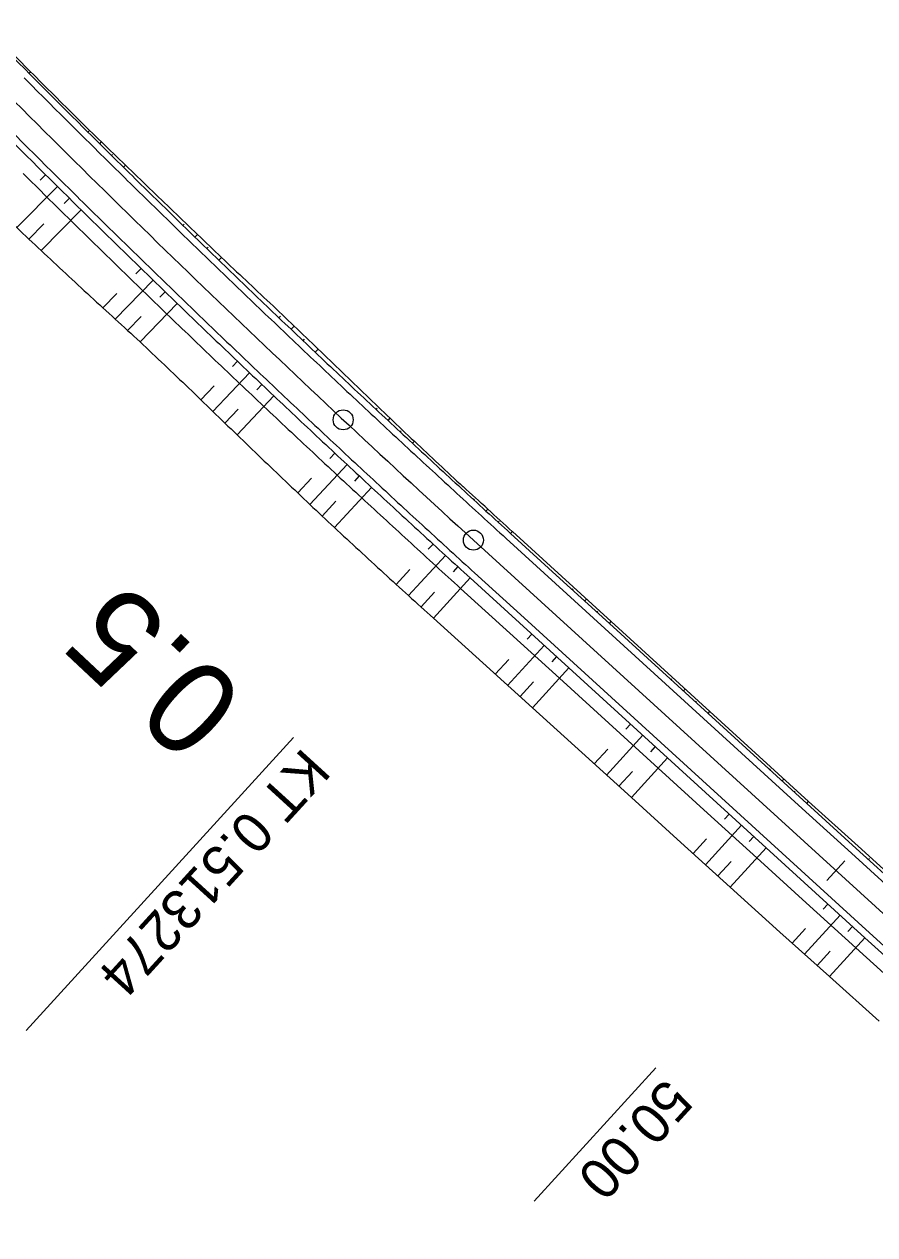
# Model space of a CAD drawing. Extents: x -481656 to -478728, y -1113199 to -1110710.
# Drawn here: x -481388.3 to -481324.6, y -1112998.4 to -1112907.7 of the extents above; entities that cross this region are included whole.
import ezdxf

# ---------------------------------------------------------------- set-up
doc = ezdxf.new("R2010")
doc.units = 0
for name, color, linetype in [('C11_HATCH_SLOPE_L', 7, 'Continuous'), ('C11_HATCH_SLOPE_R', 7, 'Continuous'), ('C11_HECTOMETRY', 7, 'Continuous'), ('C11_HLBODY', 7, 'Continuous'), ('C11_HRANA_TELESO', 7, 'Continuous'), ('C11_KORUNA', 7, 'Continuous'), ('C11_OSA', 7, 'Continuous'), ('C11_PRIKOP', 7, 'Continuous'), ('C11_STANICENI', 7, 'Continuous'), ('C11_VOZOVKA', 7, 'Continuous'), ('C11_ZPEVKRAJ', 7, 'Continuous')]:
    doc.layers.add(name, color=color, linetype=linetype)

msp = doc.modelspace()

# ---------------------------------------------------------------- linework, layer by layer
at = {"layer": 'C11_HATCH_SLOPE_L'}
for p, q in [((-481387.958, -1112911.412), (-481387.842, -1112911.297)), ((-481383.545, -1112915.818), (-481383.481, -1112915.754)), ((-481383.418, -1112915.69), (-481383.418, -1112915.69)), ((-481382.659, -1112916.696), (-481382.526, -1112916.561)), ((-481381.772, -1112917.572), (-481381.702, -1112917.501)), ((-481381.632, -1112917.43), (-481381.632, -1112917.43)), ((-481380.884, -1112918.448), (-481380.737, -1112918.299)), ((-481376.427, -1112922.81), (-481376.337, -1112922.717)), ((-481376.247, -1112922.624), (-481376.247, -1112922.624)), ((-481375.533, -1112923.679), (-481375.346, -1112923.486)), ((-481374.637, -1112924.546), (-481374.54, -1112924.446)), ((-481374.443, -1112924.346), (-481374.443, -1112924.346)), ((-481373.74, -1112925.413), (-481373.54, -1112925.206)), ((-481369.24, -1112929.73), (-481369.125, -1112929.609)), ((-481369.01, -1112929.488), (-481369.01, -1112929.488)), ((-481368.336, -1112930.59), (-481368.108, -1112930.35)), ((-481367.432, -1112931.449), (-481367.318, -1112931.33)), ((-481367.205, -1112931.21), (-481367.205, -1112931.21)), ((-481366.527, -1112932.306), (-481366.301, -1112932.068)), ((-481361.811, -1112936.394), (-481361.811, -1112936.394)), ((-481361.983, -1112936.578), (-481361.897, -1112936.486)), ((-481361.072, -1112937.429), (-481360.91, -1112937.255)), ((-481360.159, -1112938.279), (-481360.083, -1112938.198)), ((-481360.007, -1112938.116), (-481360.007, -1112938.116)), ((-481359.245, -1112939.127), (-481359.103, -1112938.975)), ((-481354.659, -1112943.353), (-481354.596, -1112943.284)), ((-481354.534, -1112943.216), (-481354.534, -1112943.216)), ((-481353.739, -1112944.195), (-481353.613, -1112944.058)), ((-481352.817, -1112945.036), (-481352.754, -1112944.968)), ((-481352.691, -1112944.899), (-481352.691, -1112944.899)), ((-481351.893, -1112945.879), (-481351.767, -1112945.741)), ((-481347.149, -1112949.952), (-481347.149, -1112949.952)), ((-481347.275, -1112950.09), (-481347.212, -1112950.021)), ((-481346.352, -1112950.933), (-481346.225, -1112950.794)), ((-481345.428, -1112951.775), (-481345.365, -1112951.706)), ((-481345.302, -1112951.636), (-481345.302, -1112951.636)), ((-481344.504, -1112952.617), (-481344.378, -1112952.478)), ((-481339.887, -1112956.829), (-481339.823, -1112956.759)), ((-481339.759, -1112956.689), (-481339.759, -1112956.689)), ((-481338.963, -1112957.671), (-481338.835, -1112957.531)), ((-481338.04, -1112958.514), (-481337.976, -1112958.444)), ((-481337.911, -1112958.373), (-481337.911, -1112958.373)), ((-481337.116, -1112959.356), (-481336.988, -1112959.215)), ((-481332.498, -1112963.568), (-481332.434, -1112963.497)), ((-481332.369, -1112963.426), (-481332.369, -1112963.426)), ((-481331.575, -1112964.41), (-481331.445, -1112964.268)), ((-481330.651, -1112965.252), (-481330.586, -1112965.181)), ((-481330.521, -1112965.11), (-481330.521, -1112965.11)), ((-481329.727, -1112966.095), (-481329.598, -1112965.952)), ((-481325.11, -1112970.306), (-481325.036, -1112970.225)), ((-481324.962, -1112970.144), (-481324.962, -1112970.144))]:
    msp.add_line(p, q, dxfattribs=at)
at = {"layer": 'C11_HATCH_SLOPE_R'}
for p, q in [((-481386.715, -1112919.012), (-481387.108, -1112919.409)), ((-481385.825, -1112919.894), (-481388.87, -1112922.972)), ((-481384.934, -1112920.775), (-481385.326, -1112921.172)), ((-481384.042, -1112921.654), (-481387.04, -1112924.699)), ((-481386.836, -1112922.702), (-481387.956, -1112923.836)), ((-481379.565, -1112926.036), (-481379.951, -1112926.432)), ((-481378.666, -1112926.909), (-481381.499, -1112929.829)), ((-481381.382, -1112927.904), (-481382.428, -1112928.98)), ((-481377.766, -1112927.78), (-481378.15, -1112928.176)), ((-481376.865, -1112928.651), (-481379.638, -1112931.524)), ((-481379.551, -1112929.625), (-481380.569, -1112930.677)), ((-481372.345, -1112932.987), (-481372.722, -1112933.383)), ((-481371.437, -1112933.851), (-481374.186, -1112936.742)), ((-481374.094, -1112934.822), (-481375.089, -1112935.866)), ((-481370.529, -1112934.714), (-481370.904, -1112935.11)), ((-481369.619, -1112935.575), (-481372.378, -1112938.491)), ((-481372.282, -1112936.562), (-481373.283, -1112937.617)), ((-481365.056, -1112939.866), (-481365.426, -1112940.262)), ((-481364.14, -1112940.721), (-481366.922, -1112943.706)), ((-481366.814, -1112941.748), (-481367.834, -1112942.84)), ((-481363.223, -1112941.574), (-481363.59, -1112941.97)), ((-481362.305, -1112942.427), (-481365.094, -1112945.435)), ((-481364.983, -1112943.468), (-481366.009, -1112944.571)), ((-481357.698, -1112946.672), (-481358.06, -1112947.067)), ((-481356.774, -1112947.517), (-481359.531, -1112950.536)), ((-481359.442, -1112948.576), (-481360.462, -1112949.69)), ((-481355.849, -1112948.361), (-481356.209, -1112948.756)), ((-481354.925, -1112949.203), (-481357.676, -1112952.219)), ((-481357.586, -1112950.265), (-481358.602, -1112951.38)), ((-481350.308, -1112953.415), (-481350.665, -1112953.806)), ((-481349.384, -1112954.257), (-481352.119, -1112957.256)), ((-481352.034, -1112955.307), (-481353.045, -1112956.416)), ((-481348.46, -1112955.1), (-481348.816, -1112955.49)), ((-481347.537, -1112955.942), (-481350.266, -1112958.935)), ((-481350.182, -1112956.988), (-481351.192, -1112958.095)), ((-481342.919, -1112960.154), (-481343.272, -1112960.541)), ((-481341.996, -1112960.996), (-481344.71, -1112963.973)), ((-481344.63, -1112962.03), (-481345.636, -1112963.133)), ((-481340.148, -1112962.681), (-481342.858, -1112965.651)), ((-481341.072, -1112961.838), (-481341.424, -1112962.224)), ((-481342.78, -1112963.712), (-481343.784, -1112964.812)), ((-481335.531, -1112966.892), (-481335.88, -1112967.275)), ((-481334.607, -1112967.735), (-481337.301, -1112970.689)), ((-481337.228, -1112968.754), (-481338.228, -1112969.85)), ((-481333.683, -1112968.577), (-481334.032, -1112968.959)), ((-481332.76, -1112969.42), (-481335.449, -1112972.368)), ((-481335.378, -1112970.434), (-481336.375, -1112971.528)), ((-481327.219, -1112974.474), (-481329.884, -1112977.396)), ((-481328.142, -1112973.631), (-481328.488, -1112974.01)), ((-481326.295, -1112975.316), (-481326.64, -1112975.694)), ((-481329.824, -1112975.474), (-481330.814, -1112976.561)), ((-481325.371, -1112976.158), (-481328.022, -1112979.065)), ((-481327.968, -1112977.15), (-481328.953, -1112978.23))]:
    msp.add_line(p, q, dxfattribs=at)
at = {"layer": 'C11_HECTOMETRY'}
msp.add_circle((-481364.432, -1112937.368), 0.75, dxfattribs=at)
at = {"layer": 'C11_HLBODY'}
msp.add_line((-481368.162, -1112961.155), (-481388.176, -1112983.098), dxfattribs=at)
msp.add_circle((-481354.685, -1112946.378), 0.75, dxfattribs=at)
at = {"layer": 'C11_HRANA_TELESO'}
for p, q in [((-481351.767, -1112945.741), (-481348.073, -1112949.11)), ((-481348.073, -1112949.11), (-481344.378, -1112952.478)), ((-481357.676, -1112952.219), (-481353.971, -1112955.577)), ((-481344.378, -1112952.478), (-481340.683, -1112955.847)), ((-481353.971, -1112955.577), (-481350.266, -1112958.935)), ((-481340.683, -1112955.847), (-481336.988, -1112959.215)), ((-481350.266, -1112958.935), (-481346.563, -1112962.294)), ((-481336.988, -1112959.215), (-481333.292, -1112962.584)), ((-481346.563, -1112962.294), (-481342.858, -1112965.651)), ((-481333.292, -1112962.584), (-481329.598, -1112965.952)), ((-481342.858, -1112965.651), (-481339.154, -1112969.01)), ((-481329.598, -1112965.952), (-481325.886, -1112969.303)), ((-481339.154, -1112969.01), (-481335.449, -1112972.368)), ((-481325.886, -1112969.303), (-481322.188, -1112972.668)), ((-481335.449, -1112972.368), (-481331.745, -1112975.727)), ((-481331.745, -1112975.727), (-481328.022, -1112979.065)), ((-481328.022, -1112979.065), (-481324.301, -1112982.404))]:
    msp.add_line(p, q, dxfattribs=at)
for centre, radius, start, end in [((-479258.593, -1110808.225), 2992.76, 224.550017, 224.645628), ((-480681.84, -1112206.504), 997.583, 224.950853, 225.237333), ((-480686.361, -1112202.081), 997.56, 225.600597, 225.887086), ((-480686.387, -1112202.11), 997.521, 225.886986, 226.173475), ((-480697.007, -1112191.858), 1006.58, 226.436722, 226.723272), ((-480686.557, -1112202.001), 997.482, 226.184886, 226.471375), ((-480699.383, -1112189.792), 1006.459, 226.902394, 227.188967), ((-480687.664, -1112201.012), 997.438, 226.556611, 226.843103), ((-480703.004, -1112186.645), 1006.319, 227.461944, 227.748556), ((-480679.681, -1112208.608), 997.418, 226.210094, 226.496575), ((-480684.812, -1112203.71), 1006.229, 226.328314, 226.614797), ((-480672.042, -1112215.887), 997.453, 225.890458, 226.176958), ((-480673.733, -1112214.328), 1006.239, 225.741017, 226.027511), ((-480672.182, -1112215.67), 997.513, 226.191403, 226.477903), ((-480674.239, -1112213.774), 1006.287, 226.070111, 226.356603), ((-480677.508, -1112210.593), 997.554, 226.9005, 227.186983), ((-480674.506, -1112213.458), 1006.331, 226.380047, 226.666536), ((-481690.021, -1113312.304), 498.782, 47.30015, 47.87359), ((-480681.85, -1112206.573), 1006.349, 227.239672, 227.526153), ((-481021.065, -1112578.22), 503.173, 227.44009, 228.0118)]:
    msp.add_arc(centre, radius, start, end, dxfattribs=at)
at = {"layer": 'C11_KORUNA'}
for p, q in [((-481351.893, -1112945.879), (-481348.199, -1112949.248)), ((-481354.925, -1112949.203), (-481351.231, -1112952.573)), ((-481348.199, -1112949.248), (-481344.504, -1112952.617)), ((-481351.231, -1112952.573), (-481347.537, -1112955.942)), ((-481344.504, -1112952.617), (-481340.81, -1112955.987)), ((-481347.537, -1112955.942), (-481343.843, -1112959.311)), ((-481340.81, -1112955.987), (-481337.116, -1112959.356)), ((-481343.843, -1112959.311), (-481340.148, -1112962.681)), ((-481337.116, -1112959.356), (-481333.422, -1112962.725)), ((-481340.148, -1112962.681), (-481336.454, -1112966.05)), ((-481333.422, -1112962.725), (-481329.727, -1112966.095)), ((-481336.454, -1112966.05), (-481332.76, -1112969.42)), ((-481329.727, -1112966.095), (-481326.033, -1112969.464)), ((-481332.76, -1112969.42), (-481329.066, -1112972.789)), ((-481326.033, -1112969.464), (-481322.339, -1112972.833)), ((-481329.066, -1112972.789), (-481325.371, -1112976.158)), ((-481325.371, -1112976.158), (-481321.677, -1112979.528))]:
    msp.add_line(p, q, dxfattribs=at)
for centre, radius, start, end in [((-479264.402, -1110801.897), 2993.25, 224.714353, 224.809956), ((-480680.814, -1112207.528), 997.75, 224.8676, 225.154081), ((-480680.814, -1112207.528), 1002.25, 224.867603, 225.154083), ((-480680.814, -1112207.528), 997.75, 225.154081, 225.440561), ((-480680.814, -1112207.528), 1002.25, 225.154081, 225.440561), ((-480680.814, -1112207.528), 997.75, 225.440561, 225.727042), ((-480680.814, -1112207.528), 1002.25, 225.440561, 225.727042), ((-480680.814, -1112207.528), 997.75, 225.727039, 226.013519), ((-480680.814, -1112207.528), 1002.25, 225.727042, 226.013522), ((-480680.814, -1112207.528), 997.75, 226.013519, 226.3), ((-480680.814, -1112207.528), 1002.25, 226.013519, 226.3), ((-480680.814, -1112207.528), 997.75, 226.3, 226.586481), ((-480680.814, -1112207.528), 1002.25, 226.3, 226.586481), ((-480680.814, -1112207.528), 997.75, 226.586478, 226.872958), ((-480680.814, -1112207.528), 1002.25, 226.586478, 226.872958), ((-480680.814, -1112207.528), 997.75, 226.872958, 227.159439), ((-480680.814, -1112207.528), 1002.25, 226.872958, 227.159439), ((-480680.814, -1112207.528), 997.75, 227.159439, 227.445919), ((-480680.814, -1112207.528), 1002.25, 227.159439, 227.445919), ((-481017.168, -1112575.966), 498.875, 227.28536, 227.85876), ((-481018.687, -1112577.626), 501.125, 227.28571, 227.85822)]:
    msp.add_arc(centre, radius, start, end, dxfattribs=at)
at = {"layer": 'C11_OSA'}
msp.add_line((-481354.685, -1112946.378), (-481297.645, -1112998.401), dxfattribs=at)
msp.add_arc((-480680.814, -1112207.528), 1000, 224.728347, 227.633472, dxfattribs=at)
at = {"layer": 'C11_PRIKOP'}
for p, q in [((-481355.644, -1112949.992), (-481351.946, -1112953.357)), ((-481351.946, -1112953.357), (-481348.248, -1112956.722)), ((-481348.248, -1112956.722), (-481344.55, -1112960.087)), ((-481344.55, -1112960.087), (-481340.852, -1112963.452)), ((-481340.852, -1112963.452), (-481337.154, -1112966.817)), ((-481337.154, -1112966.817), (-481333.455, -1112970.182)), ((-481333.455, -1112970.182), (-481329.757, -1112973.547)), ((-481329.757, -1112973.547), (-481326.059, -1112976.912)), ((-481326.059, -1112976.912), (-481322.361, -1112980.277))]:
    msp.add_line(p, q, dxfattribs=at)
for centre, radius, start, end in [((-480681.643, -1112206.709), 1003.366, 225.22065, 225.507131), ((-480681.645, -1112206.715), 1003.361, 225.506956, 225.793436), ((-480681.651, -1112206.717), 1003.355, 225.793611, 226.080092), ((-480681.655, -1112206.721), 1003.349, 226.080092, 226.366572), ((-480681.657, -1112206.728), 1003.343, 226.366397, 226.652878), ((-480681.659, -1112206.734), 1003.337, 226.652703, 226.939183), ((-480681.669, -1112206.732), 1003.331, 226.939706, 227.226186), ((-480681.669, -1112206.74), 1003.326, 227.225836, 227.512317), ((-481019.477, -1112577.627), 501.661, 227.35226, 227.92457)]:
    msp.add_arc(centre, radius, start, end, dxfattribs=at)
at = {"layer": 'C11_STANICENI'}
for p, q in [((-481328.223, -1112971.865), (-481326.876, -1112970.388)), ((-481341.027, -1112985.903), (-481350.124, -1112995.878))]:
    msp.add_line(p, q, dxfattribs=at)
at = {"layer": 'C11_VOZOVKA'}
for p, q in [((-481352.23, -1112946.248), (-481348.536, -1112949.617)), ((-481354.588, -1112948.834), (-481350.894, -1112952.203)), ((-481348.536, -1112949.617), (-481344.841, -1112952.987)), ((-481350.894, -1112952.203), (-481347.2, -1112955.573)), ((-481344.841, -1112952.987), (-481341.147, -1112956.356)), ((-481347.2, -1112955.573), (-481343.506, -1112958.942)), ((-481341.147, -1112956.356), (-481337.453, -1112959.725)), ((-481343.506, -1112958.942), (-481339.811, -1112962.311)), ((-481337.453, -1112959.725), (-481333.759, -1112963.095)), ((-481339.811, -1112962.311), (-481336.117, -1112965.681)), ((-481333.759, -1112963.095), (-481330.064, -1112966.464)), ((-481336.117, -1112965.681), (-481332.423, -1112969.05)), ((-481330.064, -1112966.464), (-481326.37, -1112969.833)), ((-481332.423, -1112969.05), (-481328.729, -1112972.419)), ((-481326.37, -1112969.833), (-481322.676, -1112973.203)), ((-481328.729, -1112972.419), (-481325.034, -1112975.789)), ((-481325.034, -1112975.789), (-481321.34, -1112979.158))]:
    msp.add_line(p, q, dxfattribs=at)
for centre, radius, start, end in [((-480680.814, -1112207.528), 998.25, 224.8676, 225.154081), ((-480680.814, -1112207.528), 1001.75, 224.867603, 225.154083), ((-480680.814, -1112207.528), 998.25, 225.154081, 225.440561), ((-480680.814, -1112207.528), 1001.75, 225.154081, 225.440561), ((-480680.814, -1112207.528), 998.25, 225.440561, 225.727042), ((-480680.814, -1112207.528), 1001.75, 225.440561, 225.727042), ((-480680.814, -1112207.528), 998.25, 225.727039, 226.013519), ((-480680.814, -1112207.528), 1001.75, 225.727039, 226.013519), ((-480680.814, -1112207.528), 998.25, 226.013519, 226.3), ((-480680.814, -1112207.528), 1001.75, 226.013519, 226.3), ((-480680.814, -1112207.528), 998.25, 226.3, 226.586481), ((-480680.814, -1112207.528), 1001.75, 226.3, 226.586481), ((-480680.814, -1112207.528), 998.25, 226.586478, 226.872958), ((-480680.814, -1112207.528), 1001.75, 226.586478, 226.872958), ((-480680.814, -1112207.528), 998.25, 226.872958, 227.159439), ((-480680.814, -1112207.528), 1001.75, 226.872958, 227.159439), ((-480680.814, -1112207.528), 998.25, 227.159439, 227.445919), ((-480680.814, -1112207.528), 1001.75, 227.159439, 227.445919), ((-481017.336, -1112576.151), 499.125, 227.28539, 227.8587), ((-481018.518, -1112577.441), 500.875, 227.28567, 227.85828)]:
    msp.add_arc(centre, radius, start, end, dxfattribs=at)
at = {"layer": 'C11_ZPEVKRAJ'}
for p, q in [((-481352.23, -1112946.248), (-481348.536, -1112949.617)), ((-481354.588, -1112948.834), (-481350.894, -1112952.203)), ((-481348.536, -1112949.617), (-481344.841, -1112952.987)), ((-481350.894, -1112952.203), (-481347.2, -1112955.573)), ((-481344.841, -1112952.987), (-481341.147, -1112956.356)), ((-481347.2, -1112955.573), (-481343.506, -1112958.942)), ((-481341.147, -1112956.356), (-481337.453, -1112959.725)), ((-481343.506, -1112958.942), (-481339.811, -1112962.311)), ((-481337.453, -1112959.725), (-481333.759, -1112963.095)), ((-481339.811, -1112962.311), (-481336.117, -1112965.681)), ((-481333.759, -1112963.095), (-481330.064, -1112966.464)), ((-481336.117, -1112965.681), (-481332.423, -1112969.05)), ((-481330.064, -1112966.464), (-481326.37, -1112969.833)), ((-481332.423, -1112969.05), (-481328.729, -1112972.419)), ((-481326.37, -1112969.833), (-481322.676, -1112973.203)), ((-481328.729, -1112972.419), (-481325.034, -1112975.789)), ((-481325.034, -1112975.789), (-481321.34, -1112979.158))]:
    msp.add_line(p, q, dxfattribs=at)
for centre, radius, start, end in [((-480680.814, -1112207.528), 998.25, 224.8676, 225.154081), ((-480680.814, -1112207.528), 1001.75, 224.867603, 225.154083), ((-480680.814, -1112207.528), 998.25, 225.154081, 225.440561), ((-480680.814, -1112207.528), 1001.75, 225.154081, 225.440561), ((-480680.814, -1112207.528), 998.25, 225.440561, 225.727042), ((-480680.814, -1112207.528), 1001.75, 225.440561, 225.727042), ((-480680.814, -1112207.528), 998.25, 225.727039, 226.013519), ((-480680.814, -1112207.528), 1001.75, 225.727039, 226.013519), ((-480680.814, -1112207.528), 998.25, 226.013519, 226.3), ((-480680.814, -1112207.528), 1001.75, 226.013519, 226.3), ((-480680.814, -1112207.528), 998.25, 226.3, 226.586481), ((-480680.814, -1112207.528), 1001.75, 226.3, 226.586481), ((-480680.814, -1112207.528), 998.25, 226.586478, 226.872958), ((-480680.814, -1112207.528), 1001.75, 226.586478, 226.872958), ((-480680.814, -1112207.528), 998.25, 226.872958, 227.159439), ((-480680.814, -1112207.528), 1001.75, 226.872958, 227.159439), ((-480680.814, -1112207.528), 998.25, 227.159439, 227.445919), ((-480680.814, -1112207.528), 1001.75, 227.159439, 227.445919), ((-481017.336, -1112576.151), 499.125, 227.28539, 227.8587), ((-481018.518, -1112577.441), 500.875, 227.28567, 227.85828)]:
    msp.add_arc(centre, radius, start, end, dxfattribs=at)

# ---------------------------------------------------------------- texts
at = {"layer": 'C11_HECTOMETRY'}
msp.add_text('0.5', height=7, rotation=136.82733, dxfattribs=at).set_placement((-481371.505, -1112958.157))
at = {"layer": 'C11_HLBODY'}
msp.add_text('KT 0.513274', height=2.999, rotation=227.63348, dxfattribs=at).set_placement((-481367.423, -1112961.828))
at = {"layer": 'C11_STANICENI'}
msp.add_text('50.00', height=3, rotation=227.63348, dxfattribs=at).set_placement((-481340.287, -1112986.577))

doc.saveas('drawing.dxf')
